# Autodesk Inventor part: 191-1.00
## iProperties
Created: 2007-06
Part Number: 191-1.00
Document SubType Name: Modeling
Designer: btaylor
Density: 1 g/cm^3
Author: btaylor
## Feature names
1. Sweep1
2. Extrusion1
3. Extrusion2
4. Fillet1
5. Fillet2
6. Fillet3
7. Fillet4
8. Chamfer1
9. Chamfer2
